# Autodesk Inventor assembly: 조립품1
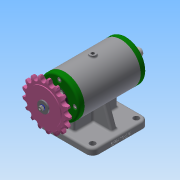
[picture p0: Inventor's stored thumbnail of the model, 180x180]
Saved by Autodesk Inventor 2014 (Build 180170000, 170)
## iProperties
Created: 2019-06
Part Number: 조립품1
Document SubType Name: Assembly
Designer: net
Author: net
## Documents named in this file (11)
- C:\Users\net\Desktop\490604V1038\답안조립품.iam
- C:\Users\net\Desktop\490604V1038\본체.ipt
- C:\Users\net\Desktop\490604V1038\베어링 6203.ipt
- C:\Users\net\Desktop\490604V1038\커버.ipt
- C:\Users\net\Desktop\490604V1038\볼트 M4.ipt
- C:\Users\net\Desktop\490604V1038\스프로킷.ipt
- C:\Users\net\Desktop\490604V1038\스프링와셔.ipt
- C:\Users\net\Desktop\490604V1038\오일 실 17 30 5.ipt
- C:\Users\net\Desktop\490604V1038\축.ipt
- C:\Users\net\Desktop\490604V1038\키 4x4x12.ipt
- C:\Users\net\Desktop\490604V1038\평와셔.ipt
